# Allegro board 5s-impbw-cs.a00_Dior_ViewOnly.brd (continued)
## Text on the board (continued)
User.45: list("[Package] BOTTOM" "Pkg to Place Keepin Spacing" "0 MIL [NONE]" "2968.44 MIL" "-2968.44 MIL" "DRC ERROR CLASS/PACKAGE_BOTTOM" "[Shape] Package Keepin/All ((9791.94 -9293.68) (17182.26 -5761.63))" "[Shape] Package Geometry/Place_Bound_Bottom ((9326.1 -2815.82) (9426.06 -2715.85))" list(9791.940000 -5761.630000) nil)@@@list("liquid_ni" "2014/02/18 09:29:22" nil "s0dcoa16607a" "5s-impbw-cs.104")@@@list("jake_ma" "2014/02/18 09:53:02" nil "s0dcoa89107" "5s-impbw-cs.104") | list("[Package] TOP" "Pkg to Place Keepin Spacing" "0 MIL [NONE]" "3167.02 MIL" "-3167.02 MIL" "DRC ERROR CLASS/PACKAGE_TOP" "[Shape] Package Keepin/All ((9791.94 -9293.68) (17182.26 -5761.63))" "[Shape] Package Geometry/Place_Bound_Top ((9326.1 -2615.82) (9426.06 -2515.85))" list(9791.940000 -5761.630000) nil)@@@list("liquid_ni" "2014/02/18 09:29:01" nil "s0dcoa16607a" "5s-impbw-cs.104")@@@list("jake_ma" "2014/02/18 09:52:38" nil "s0dcoa89107" "5s-impbw-cs.104") | list("[Package] TOP" "Pkg to Place Keepin Spacing" "0 MIL [NONE]" "3465.67 MIL" "-3465.67 MIL" "DRC ERROR CLASS/PACKAGE_TOP" "[Shape] Package Keepin/All ((9791.94 -9293.68) (17182.26 -5761.63))" "[Shape] Package Geometry/Place_Bound_Top ((9281.08 -2310.84) (9471.08 -2120.84))" list(9791.940000 -5761.630000) nil)@@@list("liquid_ni" "2014/02/18 09:29:00" nil "s0dcoa16607a" "5s-impbw-cs.104")@@@list("jake_ma" "2014/02/18 09:52:26" nil "s0dcoa89107" "5s-impbw-cs.104") | list("[Package] TOP" "Pkg to Place Keepin Spacing" "0 MIL [NONE]" "0 MIL" "0.00 MIL" "DRC ERROR CLASS/PACKAGE_TOP" "[Shape] Package Keepin/All ((9791.94 -9293.68) (17182.26 -5761.63))" "[Shape] Package Geometry/Place_Bound_Top ((9763.0 -7637.0) (9946.0 -7454.0))" list(9791.940000 -7637.000000) nil)@@@list("liquid_ni" "2014/02/18 09:29:04" nil "s0dcoa16607a" "5s-impbw-cs.104")@@@list("jake_ma" "2014/02/18 09:52:42" nil "s0dcoa89107" "5s-impbw-cs.104") | list("[Package] TOP" "Pkg to Place Keepin Spacing" "0 MIL [NONE]" "0 MIL" "0.00 MIL" "DRC ERROR CLASS/PACKAGE_TOP" "[Shape] Package Keepin/All ((9791.94 -9293.68) (17182.26 -5761.63))" "[Shape] Package Geometry/Place_Bound_Top ((9763.0 -7844.0) (9946.0 -7661.0))" list(9791.940000 -7844.000000) nil)@@@list("liquid_ni" "2014/02/18 09:29:04" nil "s0dcoa16607a" "5s-impbw-cs.104")@@@list("jake_ma" "2014/02/18 09:52:41" nil "s0dcoa89107" "5s-impbw-cs.104") | list("[Package] TOP" "Pkg to Place Keepin Spacing" "0 MIL [NONE]" "0 MIL" "0.00 MIL" "DRC ERROR CLASS/PACKAGE_TOP" "[Shape] Package Keepin/All ((9791.94 -9293.68) (17182.26 -5761.63))" "[Shape] Package Geometry/Place_Bound_Top ((9763.15 -8331.99) (9946.15 -8148.99))" list(9791.940000 -8331.990000) nil)@@@list("liquid_ni" "2014/02/18 09:28:53" nil "s0dcoa16607a" "5s-impbw-cs.104")@@@list("jake_ma" "2014/02/18 09:51:35" nil "s0dcoa89107" "5s-impbw-cs.104") | list("[Package] TOP" "Pkg to Place Keepin Spacing" "0 MIL [NONE]" "0 MIL" "0.00 MIL" "DRC ERROR CLASS/PACKAGE_TOP" "[Shape] Package Keepin/All ((9791.94 -9293.68) (17182.26 -5761.63))" "[Shape] Package Geometry/Place_Bound_Top ((9764.0 -8530.0) (9947.0 -8347.0))" list(9791.940000 -8530.000000) nil)@@@list("liquid_ni" "2014/02/18 09:29:03" nil "s0dcoa16607a" "5s-impbw-cs.104")@@@list("jake_ma" "2014/02/18 09:47:59" nil "s0dcoa89107" "5s-impbw-cs.104") | list("[Package] BOTTOM" "Pkg to Place Keepin Spacing" "0 MIL [NONE]" "365.88 MIL" "-365.88 MIL" "DRC ERROR CLASS/PACKAGE_BOTTOM" "[Shape] Package Keepin/All ((9791.94 -9293.68) (17182.26 -5761.63))" "[Shape] Package Geometry/Place_Bound_Bottom ((9326.1 -8638.67) (9426.06 -8538.7))" list(9791.940000 -8588.680000) nil)@@@list("liquid_ni" "2014/02/18 09:29:21" nil "s0dcoa16607a" "5s-impbw-cs.104")@@@list("jake_ma" "2014/02/18 09:53:01" nil "s0dcoa89107" "5s-impbw-cs.104") | list("[Package] TOP" "Pkg to Place Keepin Spacing" "0 MIL [NONE]" "0 MIL" "0.00 MIL" "DRC ERROR CLASS/PACKAGE_TOP" "[Shape] Package Keepin/All ((9791.94 -9293.68) (17182.26 -5761.63))" "[Shape] Package Geometry/Place_Bound_Top ((9763.5 -8729.0) (9947.0 -8543.0))" list(9791.940000 -8729.000000) nil)@@@list("liquid_ni" "2014/02/18 09:29:03" nil "s0dcoa16607a" "5s-impbw-cs.104")@@@list("jake_ma" "2014/02/18 09:47:58" nil "s0dcoa89107" "5s-impbw-cs.104") | list("[Package] TOP" "Pkg to Place Keepin Spacing" "0 MIL [NONE]" "365.88 MIL" "-365.88 MIL" "DRC ERROR CLASS/PACKAGE_TOP" "[Shape] Package Keepin/All ((9791.94 -9293.68) (17182.26 -5761.63))" "[Shape] Package Geometry/Place_Bound_Top ((9326.1 -8838.67) (9426.06 -8738.7))" list(9791.940000 -8788.680000) nil)@@@list("liquid_ni" "2014/02/18 09:29:01" nil "s0dcoa16607a" "5s-impbw-cs.104")@@@list("jake_ma" "2014/02/18 09:52:37" nil "s0dcoa89107" "5s-impbw-cs.104") | list("[Package] TOP" "Pkg to Place Keepin Spacing" "0 MIL [NONE]" "0 MIL" "0.00 MIL" "DRC ERROR CLASS/PACKAGE_TOP" "[Shape] Package Keepin/All ((9791.94 -9293.68) (17182.26 -5761.63))" "[Shape] Package Geometry/Place_Bound_Top ((9763.0 -8806.0) (9946.0 -8743.0))" list(9791.940000 -8806.000000) nil)@@@list("liquid_ni" "2014/02/18 09:29:02" nil "s0dcoa16607a" "5s-impbw-cs.104")@@@list("jake_ma" "2014/02/18 09:52:40" nil "s0dcoa89107" "5s-impbw-cs.104") | list("[Package] TOP" "Pkg to Place Keepin Spacing" "0 MIL [NONE]" "337.34 MIL" "-337.34 MIL" "DRC ERROR CLASS/PACKAGE_TOP" "[Shape] Package Keepin/All ((9791.94 -9293.68) (17182.26 -5761.63))" "[Shape] Package Geometry/Place_Bound_Top ((9281.08 -9233.68) (9471.08 -9043.68))" list(9791.940000 -8939.530000) nil)@@@list("liquid_ni" "2014/02/18 09:28:59" nil "s0dcoa16607a" "5s-impbw-cs.104")@@@list("jake_ma" "2014/02/18 09:52:00" nil "s0dcoa89107" "5s-impbw-cs.104") | list("[Electrical] ALL" "Diffpair Max Uncoupled Length" "200 MIL [DIFFP_UNCOUPLED_LENGTH]" "222.6 MIL" "-22.60 MIL" "DRC ERROR CLASS/ALL" "[PinPair] <uTiL>cId2972<uTiL>.37:<uTiL>cId3248<uTiL>.C22 ((9896.52 -5943.25) (10624.86 -7168.35))" "[PinPair] <uTiL>cId2972<uTiL>.38:<uTiL>cId3248<uTiL>.C23 ((9896.52 -5962.93) (10601.66 -7184.35))" list(9896.520000 -5962.930000) nil)@@@list("liquid_ni" "2014/02/18 09:28:51" nil "s0dcoa16607a" "5s-impbw-cs.104")@@@list("jake_ma" "2014/02/18 09:47:12" nil "s0dcoa89107" "5s-impbw-cs.104") | list("[Electrical] ALL" "Diffpair Max Uncoupled Length" "200 MIL [DIFFP_UNCOUPLED_LENGTH]" "235.45 MIL" "-35.45 MIL" "DRC ERROR CLASS/ALL" "[PinPair] <uTiL>cId2972<uTiL>.40:<uTiL>cId3248<uTiL>.E10 ((9896.52 -6002.3) (10657.66 -6884.13))" "[PinPair] <uTiL>cId2972<uTiL>.41:<uTiL>cId3248<uTiL>.F10 ((9896.52 -6021.99) (10683.26 -6884.13))" list(9896.520000 -6021.990000) nil)@@@list("liquid_ni" "2014/02/18 09:28:52" nil "s0dcoa16607a" "5s-impbw-cs.104")@@@list("jake_ma" "2014/02/18 09:47:14" nil "s0dcoa89107" "5s-impbw-cs.104") | list("[Electrical] ALL" "Diffpair Max Uncoupled Length" "200 MIL [DIFFP_UNCOUPLED_LENGTH]" "249.63 MIL" "-49.63 MIL" "DRC ERROR CLASS/ALL" "[PinPair] <uTiL>cId2972<uTiL>.44:<uTiL>cId3248<uTiL>.B37 ((9896.52 -6081.04) (10580.16 -7544.64))" "[PinPair] <uTiL>cId2972<uTiL>.43:<uTiL>cId3248<uTiL>.A37 ((9896.52 -6061.36) (10554.56 -7544.64))" list(9896.520000 -6061.360000) nil)@@@list("liquid_ni" "2014/02/18 09:28:49" nil "s0dcoa16607a" "5s-impbw-cs.104")@@@list("jake_ma" "2014/02/18 09:47:09" nil "s0dcoa89107" "5s-impbw-cs.104") | list("[Electrical] ALL" "Diffpair Max Uncoupled Length" "200 MIL [DIFFP_UNCOUPLED_LENGTH]" "212.84 MIL" "-12.84 MIL" "DRC ERROR CLASS/ALL" "[PinPair] <uTiL>cId3219<uTiL>.22:<uTiL>cId2972<uTiL>.58 ((11113.64 -5982.01) (9896.52 -6356.63))" "[PinPair] <uTiL>cId3219<uTiL>.23:<uTiL>cId2972<uTiL>.59 ((11093.95 -5982.01) (9896.52 -6376.32))" list(9896.520000 -6376.320000) nil)@@@list("liquid_ni" "2014/02/18 09:28:11" nil "s0dcoa16607a" "5s-impbw-cs.104")@@@list("jake_ma" "2014/02/18 09:45:26" nil "s0dcoa89107" "5s-impbw-cs.104") | list("[Package] BOTTOM" "Pkg to Pkg Spacing" "0 MIL [PACKAGE_HEIGHT_MIN]" "2 MIL" "-2.00 MIL" "DRC ERROR CLASS/PACKAGE_BOTTOM" "[Shape] Package Geometry/Place_Bound_Bottom ((9796.52 -7945.0) (10080.38 -7589.8))" "[Shape] Package Geometry/Place_Bound_Bottom ((9916.61 -7721.7) (9960.23 -7679.7))" list(9916.610000 -7589.800000) nil)@@@list("liquid_ni" "2014/02/18 09:29:14" nil "s0dcoa16607a" "5s-impbw-cs.104")@@@list("jake_ma" "2014/02/18 09:48:59" nil "s0dcoa89107" "5s-impbw-cs.104") | list("[Package] BOTTOM" "Pkg to Pkg Spacing" "0 MIL [PACKAGE_HEIGHT_MIN]" "2 MIL" "-2.00 MIL" "DRC ERROR CLASS/PACKAGE_BOTTOM" "[Shape] Package Geometry/Place_Bound_Bottom ((9796.52 -7945.0) (10080.38 -7589.8))" "[Shape] Package Geometry/Place_Bound_Bottom ((9921.48 -7856.0) (9965.1 -7814.0))" list(9965.100000 -7945.000000) nil)@@@list("liquid_ni" "2014/02/18 09:29:14" nil "s0dcoa16607a" "5s-impbw-cs.104")@@@list("jake_ma" "2014/02/18 09:49:01" nil "s0dcoa89107" "5s-impbw-cs.104") | list("[Package] BOTTOM" "Pkg to Pkg Spacing" "0 MIL [PACKAGE_HEIGHT_MIN]" "2 MIL" "-2.00 MIL" "DRC ERROR CLASS/PACKAGE_BOTTOM" "[Shape] Package Geometry/Place_Bound_Bottom ((9975.3 -8315.27) (10085.48 -8252.35))" "[Shape] Package Geometry/Place_Bound_Bottom ((9993.04 -8305.89) (10035.04 -8262.27))" list(9993.040000 -8305.890000) nil)@@@list("liquid_ni" "2014/02/18 09:29:12" nil "s0dcoa16607a" "5s-impbw-cs.104")@@@list("jake_ma" "2014/02/18 09:48:55" nil "s0dcoa89107" "5s-impbw-cs.104") | list("[Electrical] ALL" "Diffpair Max Uncoupled Length" "200 MIL [DIFFP_UNCOUPLED_LENGTH]" "339.37 MIL" "-139.37 MIL" "DRC ERROR CLASS/ALL" "[PinPair] <uTiL>cId3248<uTiL>.AN8:<uTiL>cId2972<uTiL>.6 ((11279.04 -6838.61) (10069.74 -5923.56))" "[PinPair] <uTiL>cId3248<uTiL>.AM8:<uTiL>cId2972<uTiL>.7 ((11253.44 -6838.61) (10069.74 -5943.25))" list(10069.740000 -5943.250000) nil)@@@list("liquid_ni" "2014/02/18 09:28:42" nil "s0dcoa16607a" "5s-impbw-cs.104")@@@list("jake_ma" "2014/02/18 09:46:54" nil "s0dcoa89107" "5s-impbw-cs.104") | list("[Package] BOTTOM" "Pkg to Place Keepin Spacing" "0 MIL [NONE]" "0 MIL" "0.00 MIL" "DRC ERROR CLASS/PACKAGE_BOTTOM" "[Shape] Package Keepin/All ((9791.94 -9293.68) (17182.26 -5761.63))" "[Shape] Package Geometry/Place_Bound_Bottom ((9845.01 -6480.85) (10121.25 -5740.29))" list(10085.690000 -5761.630000) nil)@@@list("liquid_ni" "2014/02/18 09:29:20" nil "s0dcoa16607a" "5s-impbw-cs.104")@@@list("jake_ma" "2014/02/18 09:52:58" nil "s0dcoa89107" "5s-impbw-cs.104") | list("[Package] BOTTOM" "Pkg to Place Keepin Spacing" "0 MIL [NONE]" "0 MIL" "0.00 MIL" "DRC ERROR CLASS/PACKAGE_BOTTOM" "[Shape] Package Keepin/All ((9791.94 -9293.68) (17182.26 -5761.63))" "[Shape] Package Geometry/Place_Bound_Bottom ((9805.48 -9358.57) (10121.48 -8964.46))" list(10121.480000 -9293.680000) nil)@@@list("liquid_ni" "2014/02/18 09:29:06" nil "s0dcoa16607a" "5s-impbw-cs.104")@@@list("jake_ma" "2014/02/18 09:52:50" nil "s0dcoa89107" "5s-impbw-cs.104") | list("[Package] TOP" "Pkg to Place Keepin Spacing" "0 MIL [NONE]" "0 MIL" "0.00 MIL" "DRC ERROR CLASS/PACKAGE_TOP" "[Shape] Package Keepin/All ((9791.94 -9293.68) (17182.26 -5761.63))" "[Shape] Package Geometry/Place_Bound_Top ((9805.48 -9358.57) (10121.48 -8964.46))" list(10121.480000 -9293.680000) nil)@@@list("liquid_ni" "2014/02/18 09:28:54" nil "s0dcoa16607a" "5s-impbw-cs.104")@@@list("jake_ma" "2014/02/18 09:51:39" nil "s0dcoa89107" "5s-impbw-cs.104") | list("[Package] TOP" "Pkg to Pkg Spacing" "0 MIL [PACKAGE_HEIGHT_MIN]" "2 MIL" "-2.00 MIL" "DRC ERROR CLASS/PACKAGE_TOP" "[Shape] Package Geometry/Place_Bound_Top ((10162.99 -7893.13) (10212.83 -7783.13))" "[Shape] Package Geometry/Place_Bound_Top ((10145.68 -7837.31) (10187.68 -7793.69))" list(10162.990000 -7837.310000) nil)@@@list("liquid_ni" "2014/02/18 09:28:58" nil "s0dcoa16607a" "5s-impbw-cs.104")@@@list("jake_ma" "2014/02/18 09:47:43" nil "s0dcoa89107" "5s-impbw-cs.104") | list("[Package] TOP" "Pkg to Pkg Spacing" "0 MIL [PACKAGE_HEIGHT_MIN]" "2 MIL" "-2.00 MIL" "DRC ERROR CLASS/PACKAGE_TOP" "[Shape] Package Geometry/Place_Bound_Top ((10162.99 -7893.13) (10212.83 -7783.13))" "[Shape] Package Geometry/Place_Bound_Top ((10147.0 -7887.81) (10189.0 -7844.19))" list(10162.990000 -7887.810000) nil)@@@list("liquid_ni" "2014/02/18 09:28:58" nil "s0dcoa16607a" "5s-impbw-cs.104")@@@list("jake_ma" "2014/02/18 09:47:44" nil "s0dcoa89107" "5s-impbw-cs.104") | list("[Package] BOTTOM" "Pkg to Place Keepin Spacing" "0 MIL [NONE]" "0 MIL" "0.00 MIL" "DRC ERROR CLASS/PACKAGE_BOTTOM" "[Shape] Package Keepin/All ((9791.94 -9293.68) (17182.26 -5761.63))" "[Shape] Package Geometry/Place_Bound_Bottom ((10179.49 -6012.42) (10495.49 -5696.42))" list(10179.490000 -5761.630000) nil)@@@list("liquid_ni" "2014/02/18 09:29:07" nil "s0dcoa16607a" "5s-impbw-cs.104")@@@list("jake_ma" "2014/02/18 09:52:51" nil "s0dcoa89107" "5s-impbw-cs.104") | list("[Package] TOP" "Pkg to Place Keepin Spacing" "0 MIL [NONE]" "0 MIL" "0.00 MIL" "DRC ERROR CLASS/PACKAGE_TOP" "[Shape] Package Keepin/All ((9791.94 -9293.68) (17182.26 -5761.63))" "[Shape] Package Geometry/Place_Bound_Top ((10179.49 -6012.42) (10495.49 -5696.42))" list(10179.490000 -5761.630000) nil)@@@list("liquid_ni" "2014/02/18 09:28:54" nil "s0dcoa16607a" "5s-impbw-cs.104")@@@list("jake_ma" "2014/02/18 09:51:40" nil "s0dcoa89107" "5s-impbw-cs.104") | list("[Package] TOP" "Pkg to Pkg Spacing" "0 MIL [PACKAGE_HEIGHT_MIN]" "39.37 MIL" "-39.37 MIL" "DRC ERROR CLASS/PACKAGE_TOP" "[Shape] Package Geometry/Place_Bound_Top ((10274.4 -6767.73) (10318.02 -6725.73))" "[Shape] Package Geometry/Place_Bound_Top ((10215.61 -6834.76) (10387.63 -6693.0))" list(10274.400000 -6767.730000) nil)@@@list("liquid_ni" "2014/02/18 09:28:57" nil "s0dcoa16607a" "5s-impbw-cs.104")@@@list("jake_ma" "2014/02/18 09:47:35" nil "s0dcoa89107" "5s-impbw-cs.104") | list("[Package] TOP" "Pkg to Pkg Spacing" "0 MIL [PACKAGE_HEIGHT_MIN]" "2 MIL" "-2.00 MIL" "DRC ERROR CLASS/PACKAGE_TOP" "[Shape] Package Geometry/Place_Bound_Top ((10275.47 -6800.66) (10319.09 -6758.66))" "[Shape] Package Geometry/Place_Bound_Top ((10274.4 -6767.73) (10318.02 -6725.73))" list(10275.470000 -6758.660000) nil)@@@list("liquid_ni" "2014/02/18 09:28:58" nil "s0dcoa16607a" "5s-impbw-cs.104")@@@list("jake_ma" "2014/02/18 09:47:45" nil "s0dcoa89107" "5s-impbw-cs.104") | list("[Package] TOP" "Pkg to Pkg Spacing" "0 MIL [PACKAGE_HEIGHT_MIN]" "39.37 MIL" "-39.37 MIL" "DRC ERROR CLASS/PACKAGE_TOP" "[Shape] Package Geometry/Place_Bound_Top ((10275.47 -6800.66) (10319.09 -6758.66))" "[Shape] Package Geometry/Place_Bound_Top ((10215.61 -6834.76) (10387.63 -6693.0))" list(10275.470000 -6800.660000) nil)@@@list("liquid_ni" "2014/02/18 09:28:56" nil "s0dcoa16607a" "5s-impbw-cs.104")@@@list("jake_ma" "2014/02/18 09:47:33" nil "s0dcoa89107" "5s-impbw-cs.104") | list("[Package] BOTTOM" "Pkg to Pkg Spacing" "0 MIL [PACKAGE_HEIGHT_MIN]" "120 MIL" "-120.00 MIL" "DRC ERROR CLASS/PACKAGE_BOTTOM" "[Shape] Package Geometry/Place_Bound_Bottom ((10490.84 -6102.57) (10971.54 -5779.49))" "[Shape] Package Geometry/Place_Bound_Bottom ((10179.49 -6012.42) (10495.49 -5696.42))" list(10495.490000 -5964.530000) nil)@@@list("liquid_ni" "2014/02/18 09:29:07" nil "s0dcoa16607a" "5s-impbw-cs.104")@@@list("jake_ma" "2014/02/18 09:48:09" nil "s0dcoa89107" "5s-impbw-cs.104") | list("[Electrical] ALL" "Diffpair Max Uncoupled Length" "200 MIL [DIFFP_UNCOUPLED_LENGTH]" "216.22 MIL" "-16.22 MIL" "DRC ERROR CLASS/ALL" "[PinPair] <uTiL>cId3248<uTiL>.B15:<uTiL>cId3240<uTiL>.2 ((10579.86 -7034.35) (16685.2 -7384.77))" "[PinPair] <uTiL>cId3248<uTiL>.A15:<uTiL>cId3240<uTiL>.1 ((10554.56 -7021.35) (16665.52 -7384.77))" list(10554.560000 -7021.350000) nil)@@@list("liquid_ni" "2014/02/18 09:28:21" nil "s0dcoa16607a" "5s-impbw-cs.104")@@@list("jake_ma" "2014/02/18 09:45:48" nil "s0dcoa89107" "5s-impbw-cs.104") | list("[Electrical] ALL" "Diffpair Max Uncoupled Length" "200 MIL [DIFFP_UNCOUPLED_LENGTH]" "226.08 MIL" "-26.08 MIL" "DRC ERROR CLASS/ALL" "[PinPair] <uTiL>cId3248<uTiL>.B45:<uTiL>cId3239<uTiL>.61 ((10580.16 -7742.08) (16287.99 -8365.55))" "[PinPair] <uTiL>cId3248<uTiL>.A45:<uTiL>cId3239<uTiL>.60 ((10554.56 -7742.08) (16287.99 -8381.3))" list(10554.560000 -7742.080000) nil)@@@list("liquid_ni" "2014/02/18 09:28:17" nil "s0dcoa16607a" "5s-impbw-cs.104")@@@list("jake_ma" "2014/02/18 09:45:39" nil "s0dcoa89107" "5s-impbw-cs.104") | list("[Electrical] ALL" "Diffpair Max Uncoupled Length" "200 MIL [DIFFP_UNCOUPLED_LENGTH]" "299.45 MIL" "-99.45 MIL" "DRC ERROR CLASS/ALL" "[PinPair] <uTiL>cId3248<uTiL>.A17:<uTiL>cId3779<uTiL>.47 ((10554.56 -7050.85) (13530.6 -8518.56))" "[PinPair] <uTiL>cId3248<uTiL>.B17:<uTiL>cId3779<uTiL>.49 ((10579.86 -7064.75) (13530.6 -8538.25))" list(10579.860000 -7064.750000) nil)@@@list("liquid_ni" "2014/02/18 09:28:19" nil "s0dcoa16607a" "5s-impbw-cs.104")@@@list("jake_ma" "2014/02/18 09:45:43" nil "s0dcoa89107" "5s-impbw-cs.104") | list("[Electrical] ALL" "Diffpair Max Uncoupled Length" "200 MIL [DIFFP_UNCOUPLED_LENGTH]" "451.68 MIL" "-251.68 MIL" "DRC ERROR CLASS/ALL" "[PinPair] <uTiL>cId3220<uTiL>.9:<uTiL>cId3248<uTiL>.A33 ((10685.32 -6063.67) (10554.56 -7445.92))" "[PinPair] <uTiL>cId3220<uTiL>.8:<uTiL>cId3248<uTiL>.B33 ((10665.63 -6063.67) (10580.16 -7445.92))" list(10580.160000 -7445.920000) nil)@@@list("liquid_ni" "2014/02/18 09:28:14" nil "s0dcoa16607a" "5s-impbw-cs.104")@@@list("jake_ma" "2014/02/18 09:45:33" nil "s0dcoa89107" "5s-impbw-cs.104") | list("[Electrical] ALL" "Diffpair Max Uncoupled Length" "200 MIL [DIFFP_UNCOUPLED_LENGTH]" "256.91 MIL" "-56.91 MIL" "DRC ERROR CLASS/ALL" "[PinPair] <uTiL>cId3248<uTiL>.B30:<uTiL>cId3778<uTiL>.35 ((10592.96 -7369.38) (16861.23 -7356.26))" "[PinPair] <uTiL>cId3248<uTiL>.C29:<uTiL>cId3778<uTiL>.37 ((10605.76 -7347.2) (16861.23 -7336.57))" list(10605.760000 -7347.200000) nil)@@@list("liquid_ni" "2014/02/18 09:28:22" nil "s0dcoa16607a" "5s-impbw-cs.104")@@@list("jake_ma" "2014/02/18 09:45:51" nil "s0dcoa89107" "5s-impbw-cs.104") | list("[Electrical] ALL" "Diffpair Max Uncoupled Length" "200 MIL [DIFFP_UNCOUPLED_LENGTH]" "768.04 MIL" "-568.04 MIL" "DRC ERROR CLASS/ALL" "[PinPair] <uTiL>cId3219<uTiL>.9:<uTiL>cId3248<uTiL>.B34 ((11113.64 -6127.67) (10592.96 -7468.1))" "[PinPair] <uTiL>cId3219<uTiL>.8:<uTiL>cId3248<uTiL>.C33 ((11093.95 -6127.67) (10605.76 -7445.92))" list(10605.760000 -7445.920000) nil)@@@list("liquid_ni" "2014/02/18 09:28:15" nil "s0dcoa16607a" "5s-impbw-cs.104")@@@list("jake_ma" "2014/02/18 09:45:35" nil "s0dcoa89107" "5s-impbw-cs.104") | list("[Electrical] ALL" "Diffpair Max Uncoupled Length" "200 MIL [DIFFP_UNCOUPLED_LENGTH]" "734.16 MIL" "-534.16 MIL" "DRC ERROR CLASS/ALL" "[PinPair] <uTiL>cId3220<uTiL>.12:<uTiL>cId3248<uTiL>.F18 ((10744.37 -6063.67) (10683.26 -7071.63))" "[PinPair] <uTiL>cId3220<uTiL>.11:<uTiL>cId3248<uTiL>.E18 ((10724.69 -6063.67) (10657.66 -7071.63))" list(10657.660000 -7071.630000) nil)@@@list("liquid_ni" "2014/02/18 09:28:11" nil "s0dcoa16607a" "5s-impbw-cs.104")@@@list("jake_ma" "2014/02/18 09:45:27" nil "s0dcoa89107" "5s-impbw-cs.104") | list("[Electrical] ALL" "Diffpair Max Uncoupled Length" "200 MIL [DIFFP_UNCOUPLED_LENGTH]" "463.4 MIL" "-263.40 MIL" "DRC ERROR CLASS/ALL" "[PinPair] <uTiL>cId3220<uTiL>.8:<uTiL>cId3248<uTiL>.B33 ((10665.63 -6063.67) (10580.16 -7445.92))" "[PinPair] <uTiL>cId3220<uTiL>.9:<uTiL>cId3248<uTiL>.A33 ((10685.32 -6063.67) (10554.56 -7445.92))" list(10685.320000 -6063.670000) nil)@@@list("liquid_ni" "2014/02/18 09:28:14" nil "s0dcoa16607a" "5s-impbw-cs.104")@@@list("jake_ma" "2014/02/18 09:45:34" nil "s0dcoa89107" "5s-impbw-cs.104") | list("[Electrical] ALL" "Diffpair Max Uncoupled Length" "200 MIL [DIFFP_UNCOUPLED_LENGTH]" "553.14 MIL" "-353.14 MIL" "DRC ERROR CLASS/ALL" "[PinPair] <uTiL>cId2640<uTiL>.4:<uTiL>cId3248<uTiL>.AR10 ((10770.56 -6069.06) (11317.44 -6891.94))" "[PinPair] <uTiL>cId2640<uTiL>.3:<uTiL>cId3248<uTiL>.AT10 ((10731.19 -6069.06) (11343.04 -6891.94))" list(10731.190000 -6069.060000) nil)@@@list("liquid_ni" "2014/02/18 09:28:20" nil "s0dcoa16607a" "5s-impbw-cs.104")@@@list("jake_ma" "2014/02/18 09:45:45" nil "s0dcoa89107" "5s-impbw-cs.104") | list("[Electrical] ALL" "Diffpair Max Uncoupled Length" "200 MIL [DIFFP_UNCOUPLED_LENGTH]" "637.12 MIL" "-437.12 MIL" "DRC ERROR CLASS/ALL" "[PinPair] <uTiL>cId3219<uTiL>.11:<uTiL>cId3248<uTiL>.G20 ((11153.01 -6127.67) (10708.86 -7109.13))" "[PinPair] <uTiL>cId3219<uTiL>.12:<uTiL>cId3248<uTiL>.H20 ((11172.69 -6127.67) (10734.46 -7109.13))" list(10734.460000 -7109.130000) nil)@@@list("liquid_ni" "2014/02/18 09:28:13" nil "s0dcoa16607a" "5s-impbw-cs.104")@@@list("jake_ma" "2014/02/18 09:45:29" nil "s0dcoa89107" "5s-impbw-cs.104") | list("[Electrical] ALL" "Diffpair Max Uncoupled Length" "200 MIL [DIFFP_UNCOUPLED_LENGTH]" "709.39 MIL" "-509.39 MIL" "DRC ERROR CLASS/ALL" "[PinPair] <uTiL>cId3220<uTiL>.11:<uTiL>cId3248<uTiL>.E18 ((10724.69 -6063.67) (10657.66 -7071.63))" "[PinPair] <uTiL>cId3220<uTiL>.12:<uTiL>cId3248<uTiL>.F18 ((10744.37 -6063.67) (10683.26 -7071.63))" list(10744.370000 -6063.670000) nil)@@@list("liquid_ni" "2014/02/18 09:28:12" nil "s0dcoa16607a" "5s-impbw-cs.104")@@@list("jake_ma" "2014/02/18 09:45:28" nil "s0dcoa89107" "5s-impbw-cs.104") | list("[Electrical] ALL" "Diffpair Max Uncoupled Length" "200 MIL [DIFFP_UNCOUPLED_LENGTH]" "242.72 MIL" "-42.72 MIL" "DRC ERROR CLASS/ALL" "[PinPair] <uTiL>cId3248<uTiL>.H5:<uTiL>cId3240<uTiL>.5 ((10734.46 -6771.63) (16744.26 -7384.77))" "[PinPair] <uTiL>cId3248<uTiL>.J5:<uTiL>cId3240<uTiL>.4 ((10760.06 -6772.63) (16724.58 -7384.77))" list(10760.060000 -6772.630000) nil)@@@list("liquid_ni" "2014/02/18 09:28:25" nil "s0dcoa16607a" "5s-impbw-cs.104")@@@list("jake_ma" "2014/02/18 09:45:55" nil "s0dcoa89107" "5s-impbw-cs.104") | list("[Electrical] ALL" "Diffpair Max Uncoupled Length" "200 MIL [DIFFP_UNCOUPLED_LENGTH]" "298.77 MIL" "-98.77 MIL" "DRC ERROR CLASS/ALL" "[PinPair] <uTiL>cId3248<uTiL>.H8:<uTiL>cId3779<uTiL>.41 ((10734.46 -6846.63) (13530.6 -8459.51))" "[PinPair] <uTiL>cId3248<uTiL>.J8:<uTiL>cId3779<uTiL>.43 ((10760.06 -6846.63) (13530.6 -8479.19))" list(10760.060000 -6846.630000) nil)@@@list("liquid_ni" "2014/02/18 09:28:17" nil "s0dcoa16607a" "5s-impbw-cs.104")@@@list("jake_ma" "2014/02/18 09:45:41" nil "s0dcoa89107" "5s-impbw-cs.104") | list("[Package] BOTTOM" "Pkg to Pkg Spacing" "0 MIL [PACKAGE_HEIGHT_MIN]" "21.65 MIL" "-21.65 MIL" "DRC ERROR CLASS/PACKAGE_BOTTOM" "[Shape] Package Geometry/Place_Bound_Bottom ((11020.5 -5868.91) (11146.88 -5797.65))" "[Shape] Package Geometry/Place_Bound_Bottom ((11022.67 -5876.59) (11144.71 -5789.97))" list(11022.670000 -5868.910000) nil)@@@list("liquid_ni" "2014/02/18 09:29:11" nil "s0dcoa16607a" "5s-impbw-cs.104")@@@list("jake_ma" "2014/02/18 09:48:52" nil "s0dcoa89107" "5s-impbw-cs.104") | list("[Electrical] ALL" "Diffpair Max Uncoupled Length" "200 MIL [DIFFP_UNCOUPLED_LENGTH]" "775.1 MIL" "-575.10 MIL" "DRC ERROR CLASS/ALL" "[PinPair] <uTiL>cId3219<uTiL>.8:<uTiL>cId3248<uTiL>.C33 ((11093.95 -6127.67) (10605.76 -7445.92))" "[PinPair] <uTiL>cId3219<uTiL>.9:<uTiL>cId3248<uTiL>.B34 ((11113.64 -6127.67) (10592.96 -7468.1))" list(11113.640000 -6127.670000) nil)@@@list("liquid_ni" "2014/02/18 09:28:16" nil "s0dcoa16607a" "5s-impbw-cs.104")@@@list("jake_ma" "2014/02/18 09:45:37" nil "s0dcoa89107" "5s-impbw-cs.104") | list("[Electrical] ALL" "Diffpair Max Uncoupled Length" "200 MIL [DIFFP_UNCOUPLED_LENGTH]" "645.86 MIL" "-445.86 MIL" "DRC ERROR CLASS/ALL" "[PinPair] <uTiL>cId3219<uTiL>.12:<uTiL>cId3248<uTiL>.H20 ((11172.69 -6127.67) (10734.46 -7109.13))" "[PinPair] <uTiL>cId3219<uTiL>.11:<uTiL>cId3248<uTiL>.G20 ((11153.01 -6127.67) (10708.86 -7109.13))" list(11153.010000 -6127.670000) nil)@@@list("liquid_ni" "2014/02/18 09:28:13" nil "s0dcoa16607a" "5s-impbw-cs.104")@@@list("jake_ma" "2014/02/18 09:45:31" nil "s0dcoa89107" "5s-impbw-cs.104") | list("[Electrical] ALL" "Diffpair Max Uncoupled Length" "200 MIL [DIFFP_UNCOUPLED_LENGTH]" "338.85 MIL" "-138.85 MIL" "DRC ERROR CLASS/ALL" "[PinPair] <uTiL>cId3248<uTiL>.AM13:<uTiL>cId3241<uTiL>.37 ((11240.64 -6967.47) (16043.27 -6653.65))" "[PinPair] <uTiL>cId3248<uTiL>.AN13:<uTiL>cId3241<uTiL>.38 ((11266.24 -6967.47) (16023.58 -6653.65))" list(11266.240000 -6967.470000) nil)@@@list("liquid_ni" "2014/02/18 09:28:44" nil "s0dcoa16607a" "5s-impbw-cs.104")@@@list("jake_ma" "2014/02/18 09:46:59" nil "s0dcoa89107" "5s-impbw-cs.104") | list("[Electrical] ALL" "Relative Propagation Delay" "R_DDR_A_CTL:G::::100.00 MIL [RELATIVE_PROPAGATION_DELAY]" "113 MIL" "" "DRC ERROR CLASS/ALL" "[PinPair] <uTiL>cId3248<uTiL>.AR32:<uTiL>cId3245<uTiL>.L1 ((11322.96 -7410.31) (12895.83 -8464.31))" "[PinPair] <uTiL>cId3248<uTiL>.AP33:<uTiL>cId3243<uTiL>.L2 ((11297.36 -7445.81) (12895.83 -7198.78))" list(11297.360000 -7445.810000) nil)@@@list("liquid_ni" "2014/02/18 09:28:29" nil "s0dcoa16607a" "5s-impbw-cs.104")@@@list("jake_ma" "2014/02/18 09:46:04" nil "s0dcoa89107" "5s-impbw-cs.104") | list("[Electrical] ALL" "Relative Propagation Delay" "R_DDR_A_CTL:G::::100.00 MIL [RELATIVE_PROPAGATION_DELAY]" "113.36 MIL" "" "DRC ERROR CLASS/ALL" "[PinPair] <uTiL>cId3248<uTiL>.AR32:<uTiL>cId3245<uTiL>.L1 ((11322.96 -7410.31) (12895.83 -8464.31))" "[PinPair] <uTiL>cId3248<uTiL>.AP33:<uTiL>cId3244<uTiL>.L2 ((11297.36 -7445.81) (12895.83 -7978.74))" list(11297.360000 -7445.810000) nil)@@@list("liquid_ni" "2014/02/18 09:28:30" nil "s0dcoa16607a" "5s-impbw-cs.104")@@@list("jake_ma" "2014/02/18 09:46:06" nil "s0dcoa89107" "5s-impbw-cs.104") | list("[Electrical] ALL" "Relative Propagation Delay" "R_DDR_A_CTL:G::::100.00 MIL [RELATIVE_PROPAGATION_DELAY]" "115.33 MIL" "" "DRC ERROR CLASS/ALL" "[PinPair] <uTiL>cId3248<uTiL>.AR32:<uTiL>cId3245<uTiL>.L1 ((11322.96 -7410.31) (12895.83 -8464.31))" "[PinPair] <uTiL>cId3248<uTiL>.AP33:<uTiL>cId3242<uTiL>.L2 ((11297.36 -7445.81) (12895.83 -6744.7))" list(11297.360000 -7445.810000) nil)@@@list("liquid_ni" "2014/02/18 09:28:28" nil "s0dcoa16607a" "5s-impbw-cs.104")@@@list("jake_ma" "2014/02/18 09:46:03" nil "s0dcoa89107" "5s-impbw-cs.104") | list("[Electrical] ALL" "Relative Propagation Delay" "R_DDR_A_CLK_U2:G:::-100.00 MIL:100.00 MIL [RELATIVE_PROPAGATION_DELAY]" "129.04 MIL" "" "DRC ERROR CLASS/ALL" "[PinPair] <uTiL>cId3248<uTiL>.AV37:<uTiL>cId3245<uTiL>.J7 ((11394.24 -7552.04) (12832.84 -8275.34))" "[PinPair] <uTiL>cId3248<uTiL>.AR32:<uTiL>cId3245<uTiL>.L1 ((11322.96 -7410.31) (12895.83 -8464.31))" list(11322.960000 -7410.310000) nil)@@@list("liquid_ni" "2014/02/18 09:28:26" nil "s0dcoa16607a" "5s-impbw-cs.104")@@@list("jake_ma" "2014/02/18 09:45:57" nil "s0dcoa89107" "5s-impbw-cs.104") | list("[Electrical] ALL" "Relative Propagation Delay" "R_DDR_A_CTL:G::::100.00 MIL [RELATIVE_PROPAGATION_DELAY]" "109.5 MIL" "" "DRC ERROR CLASS/ALL" "[PinPair] <uTiL>cId3248<uTiL>.AU43:<uTiL>cId3243<uTiL>.K9 ((11368.64 -7703.59) (12864.33 -6978.31))" "[PinPair] <uTiL>cId3248<uTiL>.AR32:<uTiL>cId3244<uTiL>.L1 ((11322.96 -7410.31) (12895.83 -8010.23))" list(11322.960000 -7410.310000) nil)@@@list("liquid_ni" "2014/02/18 09:28:28" nil "s0dcoa16607a" "5s-impbw-cs.104")@@@list("jake_ma" "2014/02/18 09:46:02" nil "s0dcoa89107" "5s-impbw-cs.104") | list("[Electrical] ALL" "Relative Propagation Delay" "R_DDR_A_CTL:G::::100.00 MIL [RELATIVE_PROPAGATION_DELAY]" "111.18 MIL" "" "DRC ERROR CLASS/ALL" "[PinPair] <uTiL>cId3248<uTiL>.AU43:<uTiL>cId3243<uTiL>.K9 ((11368.64 -7703.59) (12864.33 -6978.31))" "[PinPair] <uTiL>cId3248<uTiL>.AR32:<uTiL>cId3243<uTiL>.L1 ((11322.96 -7410.31) (12895.83 -7230.27))" list(11322.960000 -7410.310000) nil)@@@list("liquid_ni" "2014/02/18 09:28:27" nil "s0dcoa16607a" "5s-impbw-cs.104")@@@list("jake_ma" "2014/02/18 09:46:00" nil "s0dcoa89107" "5s-impbw-cs.104") | list("[Electrical] ALL" "Relative Propagation Delay" "R_DDR_A_CTL:G::::100.00 MIL [RELATIVE_PROPAGATION_DELAY]" "116.78 MIL" "" "DRC ERROR CLASS/ALL" "[PinPair] <uTiL>cId3248<uTiL>.AU43:<uTiL>cId3243<uTiL>.K9 ((11368.64 -7703.59) (12864.33 -6978.31))" "[PinPair] <uTiL>cId3248<uTiL>.AR32:<uTiL>cId3242<uTiL>.L1 ((11322.96 -7410.31) (12895.83 -6776.19))" list(11322.960000 -7410.310000) nil)@@@list("liquid_ni" "2014/02/18 09:28:26" nil "s0dcoa16607a" "5s-impbw-cs.104")@@@list("jake_ma" "2014/02/18 09:45:58" nil "s0dcoa89107" "5s-impbw-cs.104") | list("[Electrical] ALL" "Relative Propagation Delay" "R_DDR_A_CTL:G::::100.00 MIL [RELATIVE_PROPAGATION_DELAY]" "131.6 MIL" "" "DRC ERROR CLASS/ALL" "[PinPair] <uTiL>cId3248<uTiL>.AR32:<uTiL>cId3245<uTiL>.L1 ((11322.96 -7410.31) (12895.83 -8464.31))" "[PinPair] <uTiL>cId3248<uTiL>.AU43:<uTiL>cId3244<uTiL>.K9 ((11368.64 -7703.59) (12864.33 -7758.27))" list(11368.640000 -7703.590000) nil)@@@list("liquid_ni" "2014/02/18 09:28:32" nil "s0dcoa16607a" "5s-impbw-cs.104")@@@list("jake_ma" "2014/02/18 09:46:09" nil "s0dcoa89107" "5s-impbw-cs.104") | list("[Electrical] ALL" "Relative Propagation Delay" "R_DDR_A_CTL:G::::100.00 MIL [RELATIVE_PROPAGATION_DELAY]" "141.93 MIL" "" "DRC ERROR CLASS/ALL" "[PinPair] <uTiL>cId3248<uTiL>.AR32:<uTiL>cId3245<uTiL>.L1 ((11322.96 -7410.31) (12895.83 -8464.31))" "[PinPair] <uTiL>cId3248<uTiL>.AU43:<uTiL>cId3242<uTiL>.K9 ((11368.64 -7703.59) (12864.33 -6524.23))" list(11368.640000 -7703.590000) nil)@@@list("liquid_ni" "2014/02/18 09:28:31" nil "s0dcoa16607a" "5s-impbw-cs.104")@@@list("jake_ma" "2014/02/18 09:46:07" nil "s0dcoa89107" "5s-impbw-cs.104") | list("[Electrical] ALL" "Relative Propagation Delay" "R_DDR_A_CTL:G::::100.00 MIL [RELATIVE_PROPAGATION_DELAY]" "143.38 MIL" "" "DRC ERROR CLASS/ALL" "[PinPair] <uTiL>cId3248<uTiL>.AR32:<uTiL>cId3245<uTiL>.L1 ((11322.96 -7410.31) (12895.83 -8464.31))" "[PinPair] <uTiL>cId3248<uTiL>.AU43:<uTiL>cId3245<uTiL>.K9 ((11368.64 -7703.59) (12864.33 -8212.35))" list(11368.640000 -7703.590000) nil)@@@list("liquid_ni" "2014/02/18 09:28:33" nil "s0dcoa16607a" "5s-impbw-cs.104")@@@list("jake_ma" "2014/02/18 09:46:11" nil "s0dcoa89107" "5s-impbw-cs.104") | list("[Electrical] ALL" "Relative Propagation Delay" "R_DDR_A_CTL:G::::100.00 MIL [RELATIVE_PROPAGATION_DELAY]" "147.88 MIL" "" "DRC ERROR CLASS/ALL" "[PinPair] <uTiL>cId3248<uTiL>.AR32:<uTiL>cId3245<uTiL>.L1 ((11322.96 -7410.31) (12895.83 -8464.31))" "[PinPair] <uTiL>cId3248<uTiL>.AU43:<uTiL>cId3243<uTiL>.K9 ((11368.64 -7703.59) (12864.33 -6978.31))" list(11368.640000 -7703.590000) nil)@@@list("liquid_ni" "2014/02/18 09:28:31" nil "s0dcoa16607a" "5s-impbw-cs.104")@@@list("jake_ma" "2014/02/18 09:46:08" nil "s0dcoa89107" "5s-impbw-cs.104") | list("[Electrical] ALL" "Relative Propagation Delay" "R_DDR_A_CTL:G::::100.00 MIL [RELATIVE_PROPAGATION_DELAY]" "113.2 MIL" "" "DRC ERROR CLASS/ALL" "[PinPair] <uTiL>cId3248<uTiL>.AR32:<uTiL>cId3245<uTiL>.L1 ((11322.96 -7410.31) (12895.83 -8464.31))" "[PinPair] <uTiL>cId3248<uTiL>.AW43:<uTiL>cId3244<uTiL>.J9 ((11419.84 -7705.54) (12832.84 -7758.27))" list(11419.840000 -7705.540000) nil)@@@list("liquid_ni" "2014/02/18 09:28:34" nil "s0dcoa16607a" "5s-impbw-cs.104")@@@list("jake_ma" "2014/02/18 09:46:13" nil "s0dcoa89107" "5s-impbw-cs.104") | list("[Electrical] ALL" "Relative Propagation Delay" "R_DDR_A_CTL:G::::100.00 MIL [RELATIVE_PROPAGATION_DELAY]" "128.42 MIL" "" "DRC ERROR CLASS/ALL" "[PinPair] <uTiL>cId3248<uTiL>.AR32:<uTiL>cId3245<uTiL>.L1 ((11322.96 -7410.31) (12895.83 -8464.31))" "[PinPair] <uTiL>cId3248<uTiL>.AW43:<uTiL>cId3245<uTiL>.J9 ((11419.84 -7705.54) (12832.84 -8212.35))" list(11419.840000 -7705.540000) nil)@@@list("liquid_ni" "2014/02/18 09:28:35" nil "s0dcoa16607a" "5s-impbw-cs.104")@@@list("jake_ma" "2014/02/18 09:46:14" nil "s0dcoa89107" "5s-impbw-cs.104") | list("[Electrical] ALL" "Relative Propagation Delay" "R_DDR_A_CTL:G::::100.00 MIL [RELATIVE_PROPAGATION_DELAY]" "138.42 MIL" "" "DRC ERROR CLASS/ALL" "[PinPair] <uTiL>cId3248<uTiL>.AR32:<uTiL>cId3245<uTiL>.L1 ((11322.96 -7410.31) (12895.83 -8464.31))" "[PinPair] <uTiL>cId3248<uTiL>.AW43:<uTiL>cId3243<uTiL>.J9 ((11419.84 -7705.54) (12832.84 -6978.31))" list(11419.840000 -7705.540000) nil)@@@list("liquid_ni" "2014/02/18 09:28:34" nil "s0dcoa16607a" "5s-impbw-cs.104")@@@list("jake_ma" "2014/02/18 09:46:12" nil "s0dcoa89107" "5s-impbw-cs.104") | list("[Electrical] ALL" "Diffpair Max Uncoupled Length" "200 MIL [DIFFP_UNCOUPLED_LENGTH]" "401.28 MIL" "-201.28 MIL" "DRC ERROR CLASS/ALL" "[PinPair] <uTiL>cId3248<uTiL>.AN21:<uTiL>cId3188<uTiL>.169 ((11271.76 -7131.93) (12089.27 -6596.53))" "[PinPair] <uTiL>cId3248<uTiL>.AM21:<uTiL>cId3188<uTiL>.171 ((11246.16 -7131.93) (12089.27 -6572.91))" list(12089.270000 -6572.910000) nil)@@@list("liquid_ni" "2014/02/18 09:28:45" nil "s0dcoa16607a" "5s-impbw-cs.104")@@@list("jake_ma" "2014/02/18 09:47:01" nil "s0dcoa89107" "5s-impbw-cs.104") | list("[Electrical] ALL" "Diffpair Max Uncoupled Length" "200 MIL [DIFFP_UNCOUPLED_LENGTH]" "558.67 MIL" "-358.67 MIL" "DRC ERROR CLASS/ALL" "[PinPair] <uTiL>cId3248<uTiL>.AN28:<uTiL>cId3188<uTiL>.45 ((11271.76 -7315.22) (12089.27 -8155.59))" "[PinPair] <uTiL>cId3248<uTiL>.AM28:<uTiL>cId3188<uTiL>.47 ((11246.16 -7315.22) (12089.27 -8131.97))" list(12089.270000 -8131.970000) nil)@@@list("liquid_ni" "2014/02/18 09:28:40" nil "s0dcoa16607a" "5s-impbw-cs.104")@@@list("jake_ma" "2014/02/18 09:46:52" nil "s0dcoa89107" "5s-impbw-cs.104") | list("[Package] BOTTOM" "Pkg to Place Keepout Spacing" "0 MIL [NONE]" "90.55 MIL" "-90.55 MIL" "DRC ERROR CLASS/PACKAGE_BOTTOM" "[Shape] Package Keepout/Bottom ((11399.94 -9452.82) (16518.41 -9220.96))" "[Shape] Package Geometry/Place_Bound_Bottom ((12313.86 -9223.84) (12810.14 -8904.39))" list(12313.860000 -9220.960000) nil)@@@list("liquid_ni" "2014/02/18 09:29:18" nil "s0dcoa16607a" "5s-impbw-cs.104")@@@list("jake_ma" "2014/02/18 09:49:10" nil "s0dcoa89107" "5s-impbw-cs.104") | list("[Electrical] ALL" "Relative Propagation Delay" "R_DDR_B_D7:G:::-5.00 MIL:23.00 MIL [RELATIVE_PROPAGATION_DELAY]" "32.99 MIL" "" "DRC ERROR CLASS/ALL" "[PinPair] <uTiL>cId3248<uTiL>.AM18:<uTiL>cId3188<uTiL>.188 ((11246.16 -7056.93) (12412.11 -6372.12))" "[PinPair] <uTiL>cId3188<uTiL>.194:<uTiL>cId3248<uTiL>.AP18 ((12412.11 -6301.26) (11297.36 -7056.93))" list(12412.110000 -6301.260000) nil)@@@list("liquid_ni" "2014/02/18 09:28:38" nil "s0dcoa16607a" "5s-impbw-cs.104")@@@list("jake_ma" "2014/02/18 09:46:27" nil "s0dcoa89107" "5s-impbw-cs.104") | list("[Electrical] ALL" "Relative Propagation Delay" "R_DDR_B_D7:G:::-5.00 MIL:23.00 MIL [RELATIVE_PROPAGATION_DELAY]" "32.44 MIL" "" "DRC ERROR CLASS/ALL" "[PinPair] <uTiL>cId3248<uTiL>.AM18:<uTiL>cId3188<uTiL>.188 ((11246.16 -7056.93) (12412.11 -6372.12))" "[PinPair] <uTiL>cId3188<uTiL>.192:<uTiL>cId3248<uTiL>.AR18 ((12412.11 -6324.88) (11322.96 -7056.93))" list(12412.110000 -6324.880000) nil)@@@list("liquid_ni" "2014/02/18 09:28:37" nil "s0dcoa16607a" "5s-impbw-cs.104")@@@list("jake_ma" "2014/02/18 09:46:24" nil "s0dcoa89107" "5s-impbw-cs.104") | list("[Electrical] ALL" "Diffpair Max Uncoupled Length" "200 MIL [DIFFP_UNCOUPLED_LENGTH]" "472.41 MIL" "-272.41 MIL" "DRC ERROR CLASS/ALL" "[PinPair] <uTiL>cId3248<uTiL>.AN18:<uTiL>cId3188<uTiL>.186 ((11271.76 -7056.93) (12412.11 -6395.75))" "[PinPair] <uTiL>cId3248<uTiL>.AM18:<uTiL>cId3188<uTiL>.188 ((11246.16 -7056.93) (12412.11 -6372.12))" list(12412.110000 -6372.120000) nil)@@@list("liquid_ni" "2014/02/18 09:28:39" nil "s0dcoa16607a" "5s-impbw-cs.104")@@@list("jake_ma" "2014/02/18 09:46:49" nil "s0dcoa89107" "5s-impbw-cs.104") | list("[Electrical] ALL" "Diffpair Max Uncoupled Length" "200 MIL [DIFFP_UNCOUPLED_LENGTH]" "222.12 MIL" "-22.12 MIL" "DRC ERROR CLASS/ALL" "[PinPair] <uTiL>cId3248<uTiL>.AW18:<uTiL>cId3188<uTiL>.154 ((11407.04 -7083.99) (12412.11 -6773.7))" "[PinPair] <uTiL>cId3248<uTiL>.AV18:<uTiL>cId3188<uTiL>.152 ((11381.44 -7083.99) (12412.11 -6797.32))" list(12412.110000 -6797.320000) nil)@@@list("liquid_ni" "2014/02/18 09:28:36" nil "s0dcoa16607a" "5s-impbw-cs.104")@@@list("jake_ma" "2014/02/18 09:46:19" nil "s0dcoa89107" "5s-impbw-cs.104") | list("[Electrical] ALL" "Diffpair Phase Tolerance" "5 [DIFFP_PHASE_TOL]" "19.83 MIL" "-14.83 MIL" "DRC ERROR CLASS/ALL" "[PinPair] <uTiL>cId3243<uTiL>.C7:<uTiL>cId3248<uTiL>.AW53 ((12643.86 -7041.3) (11407.04 -7942.09))" "[PinPair] <uTiL>cId3243<uTiL>.B7:<uTiL>cId3248<uTiL>.AV53 ((12612.37 -7041.3) (11381.44 -7942.09))" list(12612.370000 -7041.300000) nil)@@@list("liquid_ni" "2014/02/18 09:28:46" nil "s0dcoa16607a" "5s-impbw-cs.104")@@@list("jake_ma" "2014/02/18 09:47:02" nil "s0dcoa89107" "5s-impbw-cs.104") | list("[Electrical] ALL" "Relative Propagation Delay" "R_DDR_A_D5DQS:G:::0.00 MIL:1.00 MIL [RELATIVE_PROPAGATION_DELAY]" "19.83 MIL" "" "DRC ERROR CLASS/ALL" "[PinPair] <uTiL>cId3243<uTiL>.C7:<uTiL>cId3248<uTiL>.AW53 ((12643.86 -7041.3) (11407.04 -7942.09))" "[PinPair] <uTiL>cId3243<uTiL>.B7:<uTiL>cId3248<uTiL>.AV53 ((12612.37 -7041.3) (11381.44 -7942.09))" list(12612.370000 -7041.300000) nil)@@@list("liquid_ni" "2014/02/18 09:28:37" nil "s0dcoa16607a" "5s-impbw-cs.104")@@@list("jake_ma" "2014/02/18 09:46:21" nil "s0dcoa89107" "5s-impbw-cs.104") | list("[Electrical] ALL" "Diffpair Max Uncoupled Length" "200 MIL [DIFFP_UNCOUPLED_LENGTH]" "212.41 MIL" "-12.41 MIL" "DRC ERROR CLASS/ALL" "[PinPair] <uTiL>cId3248<uTiL>.AV57:<uTiL>cId3243<uTiL>.G3 ((11381.44 -8037.79) (12769.85 -7167.28))" "[PinPair] <uTiL>cId3248<uTiL>.AW57:<uTiL>cId3243<uTiL>.F3 ((11407.04 -8037.79) (12738.35 -7167.28))" list(12738.350000 -7167.280000) nil)@@@list("liquid_ni" "2014/02/18 09:28:48" nil "s0dcoa16607a" "5s-impbw-cs.104")@@@list("jake_ma" "2014/02/18 09:47:07" nil "s0dcoa89107" "5s-impbw-cs.104") | list("[Electrical] ALL" "Diffpair Max Uncoupled Length" "200 MIL [DIFFP_UNCOUPLED_LENGTH]" "267.37 MIL" "-67.37 MIL" "DRC ERROR CLASS/ALL" "[PinPair] <uTiL>cId1645<uTiL>.42:<uTiL>cId3248<uTiL>.B35 ((12789.27 -8932.25) (10580.16 -7490.28))" "[PinPair] <uTiL>cId1645<uTiL>.40:<uTiL>cId3248<uTiL>.A35 ((12769.58 -8932.25) (10554.56 -7490.28))" list(12769.580000 -8932.250000) nil)@@@list("liquid_ni" "2014/02/18 09:28:20" nil "s0dcoa16607a" "5s-impbw-cs.104")@@@list("jake_ma" "2014/02/18 09:45:46" nil "s0dcoa89107" "5s-impbw-cs.104") | list("[Electrical] ALL" "Diffpair Max Uncoupled Length" "200 MIL [DIFFP_UNCOUPLED_LENGTH]" "237.45 MIL" "-37.45 MIL" "DRC ERROR CLASS/ALL" "[PinPair] <uTiL>cId3242<uTiL>.F3:<uTiL>cId3248<uTiL>.AL49 ((12738.35 -6713.2) (11220.56 -7840.75))" "[PinPair] <uTiL>cId3242<uTiL>.G3:<uTiL>cId3248<uTiL>.AL48 ((12769.85 -6713.2) (11220.56 -7805.25))" list(12769.850000 -6713.200000) nil)@@@list("liquid_ni" "2014/02/18 09:28:47" nil "s0dcoa16607a" "5s-impbw-cs.104")@@@list("jake_ma" "2014/02/18 09:47:06" nil "s0dcoa89107" "5s-impbw-cs.104") | list("[Package] TOP" "Pkg to Place Keepout Spacing" "0 MIL [PACKAGE_HEIGHT_MIN]" "78.74 MIL" "-78.74 MIL" "DRC ERROR CLASS/PACKAGE_TOP" "[Shape] Package Geometry/Place_Bound_Top ((12910.41 -6356.26) (13410.81 -6033.03))" "[Shape] Package Keepout/Top ((13074.0 -6073.58) (13476.0 -5871.58))" list(13094.080000 -6033.030000) nil)@@@list("liquid_ni" "2014/02/18 09:28:52" nil "s0dcoa16607a" "5s-impbw-cs.104")@@@list("jake_ma" "2014/02/18 09:47:16" nil "s0dcoa89107" "5s-impbw-cs.104") | list("[Package] BOTTOM" "Pkg to Place Keepin Spacing" "0 MIL [NONE]" "0 MIL" "0.00 MIL" "DRC ERROR CLASS/PACKAGE_BOTTOM" "[Shape] Package Keepin/All ((9791.94 -9293.68) (17182.26 -5761.63))" "[Shape] Package Geometry/Place_Bound_Bottom ((13137.99 -6005.59) (13412.01 -5744.04))" list(13137.990000 -5761.630000) nil)@@@list("liquid_ni" "2014/02/18 09:29:05" nil "s0dcoa16607a" "5s-impbw-cs.104")@@@list("jake_ma" "2014/02/18 09:52:46" nil "s0dcoa89107" "5s-impbw-cs.104") | list("[Package] TOP" "Pkg to Pkg Spacing" "0 MIL [PACKAGE_HEIGHT_MIN]" "2 MIL" "-2.00 MIL" "DRC ERROR CLASS/PACKAGE_TOP" "[Shape] Package Geometry/Place_Bound_Top ((13318.76 -7290.79) (13358.76 -7217.59))" "[Shape] Package Geometry/Place_Bound_Top ((13335.0 -7293.81) (13377.0 -7250.19))" list(13358.760000 -7250.190000) nil)@@@list("liquid_ni" "2014/02/18 09:28:57" nil "s0dcoa16607a" "5s-impbw-cs.104")@@@list("jake_ma" "2014/02/18 09:47:42" nil "s0dcoa89107" "5s-impbw-cs.104") | list("[Package] BOTTOM" "Pkg to Pkg Spacing" "0 MIL [PACKAGE_HEIGHT_MIN]" "120 MIL" "-120.00 MIL" "DRC ERROR CLASS/PACKAGE_BOTTOM" "[Shape] Package Geometry/Place_Bound_Bottom ((13463.4 -7315.0) (13657.5 -6953.98))" "[Shape] Package Geometry/Place_Bound_Bottom ((13447.4 -7626.88) (13763.4 -7310.88))" list(13463.400000 -7315.000000) nil)@@@list("liquid_ni" "2014/02/18 09:29:08" nil "s0dcoa16607a" "5s-impbw-cs.104")@@@list("jake_ma" "2014/02/18 09:48:12" nil "s0dcoa89107" "5s-impbw-cs.104") | list("[Package] BOTTOM" "Pkg to Pkg Spacing" "0 MIL [PACKAGE_HEIGHT_MIN]" "2 MIL" "-2.00 MIL" "DRC ERROR CLASS/PACKAGE_BOTTOM" "[Shape] Package Geometry/Place_Bound_Bottom ((13463.4 -7315.0) (13657.5 -6953.98))" "[Shape] Package Geometry/Place_Bound_Bottom ((13544.83 -6984.5) (13588.45 -6942.5))" list(13544.830000 -6953.980000) nil)@@@list("liquid_ni" "2014/02/18 09:29:15" nil "s0dcoa16607a" "5s-impbw-cs.104")@@@list("jake_ma" "2014/02/18 09:49:03" nil "s0dcoa89107" "5s-impbw-cs.104") | list("[Package] BOTTOM" "Pkg to Pkg Spacing" "0 MIL [PACKAGE_HEIGHT_MIN]" "120 MIL" "-120.00 MIL" "DRC ERROR CLASS/PACKAGE_BOTTOM" "[Shape] Package Geometry/Place_Bound_Bottom ((13658.54 -7316.0) (13942.4 -6941.8))" "[Shape] Package Geometry/Place_Bound_Bottom ((13447.4 -7626.88) (13763.4 -7310.88))" list(13658.540000 -7316.000000) nil)@@@list("liquid_ni" "2014/02/18 09:29:08" nil "s0dcoa16607a" "5s-impbw-cs.104")@@@list("jake_ma" "2014/02/18 09:48:26" nil "s0dcoa89107" "5s-impbw-cs.104") | list("[Package] BOTTOM" "Pkg to Pkg Spacing" "0 MIL [PACKAGE_HEIGHT_MIN]" "2 MIL" "-2.00 MIL" "DRC ERROR CLASS/PACKAGE_BOTTOM" "[Shape] Package Geometry/Place_Bound_Bottom ((13879.91 -8970.46) (13990.09 -8907.54))" "[Shape] Package Geometry/Place_Bound_Bottom ((13929.0 -8961.81) (13971.0 -8918.19))" list(13929.000000 -8961.810000) nil)@@@list("liquid_ni" "2014/02/18 09:29:13" nil "s0dcoa16607a" "5s-impbw-cs.104")@@@list("jake_ma" "2014/02/18 09:48:58" nil "s0dcoa89107" "5s-impbw-cs.104") | list("[Package] BOTTOM" "Pkg to Pkg Spacing" "0 MIL [PACKAGE_HEIGHT_MIN]" "2 MIL" "-2.00 MIL" "DRC ERROR CLASS/PACKAGE_BOTTOM" "[Shape] Package Geometry/Place_Bound_Bottom ((13986.66 -9216.11) (14049.58 -9105.93))" "[Shape] Package Geometry/Place_Bound_Bottom ((14028.18 -9149.91) (14070.18 -9106.29))" list(14049.580000 -9149.910000) nil)@@@list("liquid_ni" "2014/02/18 09:29:13" nil "s0dcoa16607a" "5s-impbw-cs.104")@@@list("jake_ma" "2014/02/18 09:48:57" nil "s0dcoa89107" "5s-impbw-cs.104") | list("[Package] BOTTOM" "Pkg to Pkg Spacing" "0 MIL [PACKAGE_HEIGHT_MIN]" "118.11 MIL" "-118.11 MIL" "DRC ERROR CLASS/PACKAGE_BOTTOM" "[Shape] Package Geometry/Place_Bound_Bottom ((14028.18 -9149.91) (14070.18 -9106.29))" "[Shape] Package Geometry/Place_Bound_Bottom ((14054.44 -9113.78) (14307.0 -8904.72))" list(14070.180000 -9106.290000) nil)@@@list("liquid_ni" "2014/02/18 09:29:05" nil "s0dcoa16607a" "5s-impbw-cs.104")@@@list("jake_ma" "2014/02/18 09:48:06" nil "s0dcoa89107" "5s-impbw-cs.104") | list("[Package] BOTTOM" "Pkg to Pkg Spacing" "0 MIL [PACKAGE_HEIGHT_MIN]" "2 MIL" "-2.00 MIL" "DRC ERROR CLASS/PACKAGE_BOTTOM" "[Shape] Package Geometry/Place_Bound_Bottom ((14425.91 -7177.14) (14667.57 -7035.4))" "[Shape] Package Geometry/Place_Bound_Bottom ((14494.96 -7115.33) (14536.96 -7071.71))" list(14494.960000 -7115.330000) nil)@@@list("liquid_ni" "2014/02/18 09:29:15" nil "s0dcoa16607a" "5s-impbw-cs.104")@@@list("jake_ma" "2014/02/18 09:49:04" nil "s0dcoa89107" "5s-impbw-cs.104") | list("[Package] BOTTOM" "Pkg to Pkg Spacing" "0 MIL [PACKAGE_HEIGHT_MIN]" "39.37 MIL" "-39.37 MIL" "DRC ERROR CLASS/PACKAGE_BOTTOM" "[Shape] Package Geometry/Place_Bound_Bottom ((14988.03 -6580.0) (15031.65 -6538.0))" "[Shape] Package Geometry/Place_Bound_Bottom ((14915.59 -6647.0) (15087.61 -6505.24))" list(14988.030000 -6580.000000) nil)@@@list("liquid_ni" "2014/02/18 09:29:10" nil "s0dcoa16607a" "5s-impbw-cs.104")@@@list("jake_ma" "2014/02/18 09:48:50" nil "s0dcoa89107" "5s-impbw-cs.104") | list("[Package] BOTTOM" "Pkg to Pkg Spacing" "0 MIL [PACKAGE_HEIGHT_MIN]" "2 MIL" "-2.00 MIL" "DRC ERROR CLASS/PACKAGE_BOTTOM" "[Shape] Package Geometry/Place_Bound_Bottom ((14988.73 -6613.0) (15032.35 -6571.0))" "[Shape] Package Geometry/Place_Bound_Bottom ((14988.03 -6580.0) (15031.65 -6538.0))" list(14988.730000 -6571.000000) nil)@@@list("liquid_ni" "2014/02/18 09:29:16" nil "s0dcoa16607a" "5s-impbw-cs.104")@@@list("jake_ma" "2014/02/18 09:49:05" nil "s0dcoa89107" "5s-impbw-cs.104") | list("[Package] BOTTOM" "Pkg to Pkg Spacing" "0 MIL [PACKAGE_HEIGHT_MIN]" "39.37 MIL" "-39.37 MIL" "DRC ERROR CLASS/PACKAGE_BOTTOM" "[Shape] Package Geometry/Place_Bound_Bottom ((14988.73 -6613.0) (15032.35 -6571.0))" "[Shape] Package Geometry/Place_Bound_Bottom ((14915.59 -6647.0) (15087.61 -6505.24))" list(14988.730000 -6613.000000) nil)@@@list("liquid_ni" "2014/02/18 09:29:10" nil "s0dcoa16607a" "5s-impbw-cs.104")@@@list("jake_ma" "2014/02/18 09:48:49" nil "s0dcoa89107" "5s-impbw-cs.104") | list("[Package] BOTTOM" "Pkg to Pkg Spacing" "0 MIL [PACKAGE_HEIGHT_MIN]" "2 MIL" "-2.00 MIL" "DRC ERROR CLASS/PACKAGE_BOTTOM" "[Shape] Package Geometry/Place_Bound_Bottom ((14967.94 -7108.98) (15209.6 -6967.24))" "[Shape] Package Geometry/Place_Bound_Bottom ((15036.71 -7044.21) (15078.71 -7000.59))" list(15036.710000 -7044.210000) nil)@@@list("liquid_ni" "2014/02/18 09:29:16" nil "s0dcoa16607a" "5s-impbw-cs.104")@@@list("jake_ma" "2014/02/18 09:49:06" nil "s0dcoa89107" "5s-impbw-cs.104") | list("[Package] BOTTOM" "Pkg to Pkg Spacing" "0 MIL [PACKAGE_HEIGHT_MIN]" "2 MIL" "-2.00 MIL" "DRC ERROR CLASS/PACKAGE_BOTTOM" "[Shape] Package Geometry/Place_Bound_Bottom ((15037.09 -7078.02) (15079.09 -7034.4))" "[Shape] Package Geometry/Place_Bound_Bottom ((15036.71 -7044.21) (15078.71 -7000.59))" list(15037.090000 -7034.400000) nil)@@@list("liquid_ni" "2014/02/18 09:29:17" nil "s0dcoa16607a" "5s-impbw-cs.104")@@@list("jake_ma" "2014/02/18 09:49:08" nil "s0dcoa89107" "5s-impbw-cs.104") | list("[Package] BOTTOM" "Pkg to Pkg Spacing" "0 MIL [PACKAGE_HEIGHT_MIN]" "2 MIL" "-2.00 MIL" "DRC ERROR CLASS/PACKAGE_BOTTOM" "[Shape] Package Geometry/Place_Bound_Bottom ((14967.94 -7108.98) (15209.6 -6967.24))" "[Shape] Package Geometry/Place_Bound_Bottom ((15037.09 -7078.02) (15079.09 -7034.4))" list(15037.090000 -7078.020000) nil)@@@list("liquid_ni" "2014/02/18 09:29:17" nil "s0dcoa16607a" "5s-impbw-cs.104")@@@list("jake_ma" "2014/02/18 09:49:09" nil "s0dcoa89107" "5s-impbw-cs.104") | list("[Electrical] ALL" "Diffpair Max Uncoupled Length" "200 MIL [DIFFP_UNCOUPLED_LENGTH]" "318.35 MIL" "-118.35 MIL" "DRC ERROR CLASS/ALL" "[PinPair] <uTiL>cId3202<uTiL>.2:<uTiL>cId3248<uTiL>.AP8 ((15978.22 -5827.3) (11304.64 -6838.61))" "[PinPair] <uTiL>cId3202<uTiL>.3:<uTiL>cId3248<uTiL>.AR8 ((15978.22 -5858.79) (11330.24 -6838.61))" list(15978.220000 -5858.790000) nil)@@@list("liquid_ni" "2014/02/18 09:28:24" nil "s0dcoa16607a" "5s-impbw-cs.104")@@@list("jake_ma" "2014/02/18 09:45:53" nil "s0dcoa89107" "5s-impbw-cs.104") | list("[Package] BOTTOM" "Pkg to Place Keepin Spacing" "0 MIL [NONE]" "0 MIL" "0.00 MIL" "DRC ERROR CLASS/PACKAGE_BOTTOM" "[Shape] Package Keepin/All ((9791.94 -9293.68) (17182.26 -5761.63))" "[Shape] Package Geometry/Place_Bound_Bottom ((15843.14 -6197.45) (16022.72 -5709.11))" list(15987.270000 -5761.630000) nil)@@@list("liquid_ni" "2014/02/18 09:29:18" nil "s0dcoa16607a" "5s-impbw-cs.104")@@@list("jake_ma" "2014/02/18 09:52:54" nil "s0dcoa89107" "5s-impbw-cs.104") | list("[Package] BOTTOM" "Pkg to Pkg Spacing" "0 MIL [PACKAGE_HEIGHT_MIN]" "21.65 MIL" "-21.65 MIL" "DRC ERROR CLASS/PACKAGE_BOTTOM" "[Shape] Package Geometry/Place_Bound_Bottom ((16076.49 -6041.88) (16147.75 -5915.5))" "[Shape] Package Geometry/Place_Bound_Bottom ((16068.81 -6039.71) (16155.43 -5917.67))" list(16076.490000 -6039.710000) nil)@@@list("liquid_ni" "2014/02/18 09:29:12" nil "s0dcoa16607a" "5s-impbw-cs.104")@@@list("jake_ma" "2014/02/18 09:48:54" nil "s0dcoa89107" "5s-impbw-cs.104") | list("[Electrical] ALL" "Diffpair Max Uncoupled Length" "200 MIL [DIFFP_UNCOUPLED_LENGTH]" "204.06 MIL" "-4.06 MIL" "DRC ERROR CLASS/ALL" "[PinPair] <uTiL>cId3239<uTiL>.6:<uTiL>cId3248<uTiL>.B47 ((16175.79 -8284.85) (10580.16 -7786.44))" "[PinPair] <uTiL>cId3239<uTiL>.7:<uTiL>cId3248<uTiL>.A47 ((16160.04 -8284.85) (10554.56 -7786.44))" list(16160.040000 -8284.850000) nil)@@@list("liquid_ni" "2014/02/18 09:28:10" nil "s0dcoa16607a" "5s-impbw-cs.104")@@@list("jake_ma" "2014/02/18 09:45:24" nil "s0dcoa89107" "5s-impbw-cs.104") | list("[Electrical] ALL" "Diffpair Max Uncoupled Length" "200 MIL [DIFFP_UNCOUPLED_LENGTH]" "286.81 MIL" "-86.81 MIL" "DRC ERROR CLASS/ALL" "[PinPair] <uTiL>cId3248<uTiL>.A45:<uTiL>cId3239<uTiL>.60 ((10554.56 -7742.08) (16287.99 -8381.3))" "[PinPair] <uTiL>cId3248<uTiL>.B45:<uTiL>cId3239<uTiL>.61 ((10580.16 -7742.08) (16287.99 -8365.55))" list(16287.990000 -8365.550000) nil)@@@list("liquid_ni" "2014/02/18 09:28:16" nil "s0dcoa16607a" "5s-impbw-cs.104")@@@list("jake_ma" "2014/02/18 09:45:38" nil "s0dcoa89107" "5s-impbw-cs.104") | list("[Package] BOTTOM" "Pkg to Place Keepin Spacing" "0 MIL [NONE]" "0 MIL" "0.00 MIL" "DRC ERROR CLASS/PACKAGE_BOTTOM" "[Shape] Package Keepin/All ((9791.94 -9293.68) (17182.26 -5761.63))" "[Shape] Package Geometry/Place_Bound_Bottom ((15402.31 -9134.22) (16493.13 -8942.31))" list(16473.600000 -9134.220000) nil)@@@list("liquid_ni" "2014/02/18 09:29:20" nil "s0dcoa16607a" "5s-impbw-cs.104")@@@list("jake_ma" "2014/02/18 09:52:57" nil "s0dcoa89107" "5s-impbw-cs.104") | list("[Electrical] ALL" "Diffpair Max Uncoupled Length" "200 MIL [DIFFP_UNCOUPLED_LENGTH]" "297.92 MIL" "-97.92 MIL" "DRC ERROR CLASS/ALL" "[PinPair] <uTiL>cId3778<uTiL>.34:<uTiL>cId3248<uTiL>.C55 ((16563.0 -7366.1) (10605.76 -7983.88))" "[PinPair] <uTiL>cId3778<uTiL>.32:<uTiL>cId3248<uTiL>.C54 ((16563.0 -7385.79) (10618.56 -7961.7))" list(16563.000000 -7385.790000) nil)@@@list("liquid_ni" "2014/02/18 09:28:09" nil "s0dcoa16607a" "5s-impbw-cs.104")@@@list("jake_ma" "2014/02/18 09:45:23" nil "s0dcoa89107" "5s-impbw-cs.104") | list("[Electrical] ALL" "Diffpair Max Uncoupled Length" "200 MIL [DIFFP_UNCOUPLED_LENGTH]" "320.28 MIL" "-120.28 MIL" "DRC ERROR CLASS/ALL" "[PinPair] <uTiL>cId3778<uTiL>.26:<uTiL>cId3248<uTiL>.B58 ((16563.0 -7444.84) (10592.96 -8060.42))" "[PinPair] <uTiL>cId3778<uTiL>.28:<uTiL>cId3248<uTiL>.C58 ((16563.0 -7425.16) (10618.56 -8060.42))" list(16563.000000 -7425.160000) nil)@@@list("liquid_ni" "2014/02/18 09:28:05" nil "s0dcoa16607a" "5s-impbw-cs.104")@@@list("jake_ma" "2014/02/18 09:45:15" nil "s0dcoa89107" "5s-impbw-cs.104") | list("[Package] BOTTOM" "Pkg to Pkg Spacing" "0 MIL [PACKAGE_HEIGHT_MIN]" "120 MIL" "-120.00 MIL" "DRC ERROR CLASS/PACKAGE_BOTTOM" "[Shape] Package Geometry/Place_Bound_Bottom ((16539.92 -6035.67) (17205.92 -5767.29))" "[Shape] Package Geometry/Place_Bound_Bottom ((16852.93 -6307.5) (17247.26 -6031.28))" list(16852.930000 -6035.670000) nil)@@@list("liquid_ni" "2014/02/18 09:29:09" nil "s0dcoa16607a" "5s-impbw-cs.104")@@@list("jake_ma" "2014/02/18 09:48:41" nil "s0dcoa89107" "5s-impbw-cs.104") | list("[Electrical] ALL" "Diffpair Max Uncoupled Length" "200 MIL [DIFFP_UNCOUPLED_LENGTH]" "264.36 MIL" "-64.36 MIL" "DRC ERROR CLASS/ALL" "[PinPair] <uTiL>cId3778<uTiL>.27:<uTiL>cId3248<uTiL>.A55 ((16861.23 -7435.0) (10554.56 -7983.88))" "[PinPair] <uTiL>cId3778<uTiL>.25:<uTiL>cId3248<uTiL>.B55 ((16861.23 -7454.68) (10580.16 -7983.88))" list(16861.230000 -7454.680000) nil)@@@list("liquid_ni" "2014/02/18 09:28:08" nil "s0dcoa16607a" "5s-impbw-cs.104")@@@list("jake_ma" "2014/02/18 09:45:20" nil "s0dcoa89107" "5s-impbw-cs.104") | list("[Electrical] ALL" "Diffpair Max Uncoupled Length" "200 MIL [DIFFP_UNCOUPLED_LENGTH]" "216.2 MIL" "-16.20 MIL" "DRC ERROR CLASS/ALL" "[PinPair] <uTiL>cId3778<uTiL>.21:<uTiL>cId3248<uTiL>.B57 ((16861.23 -7494.05) (10580.16 -8038.24))" "[PinPair] <uTiL>cId3778<uTiL>.19:<uTiL>cId3248<uTiL>.A57 ((16861.23 -7513.74) (10554.56 -8038.24))" list(16861.230000 -7513.740000) nil)@@@list("liquid_ni" "2014/02/18 09:28:07" nil "s0dcoa16607a" "5s-impbw-cs.104")@@@list("jake_ma" "2014/02/18 09:45:17" nil "s0dcoa89107" "5s-impbw-cs.104") | list("[Electrical] ALL" "Diffpair Max Uncoupled Length" "200 MIL [DIFFP_UNCOUPLED_LENGTH]" "404.24 MIL" "-204.24 MIL" "DRC ERROR CLASS/ALL" "[PinPair] <uTiL>cId3248<uTiL>.AN11:<uTiL>cId3778<uTiL>.3 ((11279.04 -6914.14) (16861.23 -7671.22))" "[PinPair] <uTiL>cId3248<uTiL>.AP11:<uTiL>cId3778<uTiL>.5 ((11304.64 -6914.14) (16861.23 -7651.53))" list(16861.230000 -7651.530000) nil)@@@list("liquid_ni" "2014/02/18 09:28:43" nil "s0dcoa16607a" "5s-impbw-cs.104")@@@list("jake_ma" "2014/02/18 09:46:56" nil "s0dcoa89107" "5s-impbw-cs.104") | list("[Package] TOP" "Pkg to Place Keepout Spacing" "0 MIL [PACKAGE_HEIGHT_MIN]" "120 MIL" "-120.00 MIL" "DRC ERROR CLASS/PACKAGE_TOP" "[Shape] Package Keepout/Top ((16990.59 -7288.27) (17272.59 -6257.16))" "[Shape] Package Geometry/Place_Bound_Top ((16852.93 -6307.5) (17247.26 -6031.28))" list(17012.640000 -6307.500000) nil)@@@list("liquid_ni" "2014/02/18 09:28:55" nil "s0dcoa16607a" "5s-impbw-cs.104")@@@list("jake_ma" "2014/02/18 09:47:31" nil "s0dcoa89107" "5s-impbw-cs.104") | list("[Package] BOTTOM" "Pkg to Place Keepin Spacing" "0 MIL [NONE]" "0 MIL" "0.00 MIL" "DRC ERROR CLASS/PACKAGE_BOTTOM" "[Shape] Package Keepin/All ((9791.94 -9293.68) (17182.26 -5761.63))" "[Shape] Package Geometry/Place_Bound_Bottom ((16813.55 -9201.2) (17129.15 -8806.86))" list(17088.570000 -8806.860000) nil)@@@list("liquid_ni" "2014/02/18 09:29:06" nil "s0dcoa16607a" "5s-impbw-cs.104")@@@list("jake_ma" "2014/02/18 09:52:47" nil "s0dcoa89107" "5s-impbw-cs.104") | list("[Package] TOP" "Pkg to Place Keepin Spacing" "0 MIL [NONE]" "0 MIL" "0.00 MIL" "DRC ERROR CLASS/PACKAGE_TOP" "[Shape] Package Keepin/All ((9791.94 -9293.68) (17182.26 -5761.63))" "[Shape] Package Geometry/Place_Bound_Top ((16813.55 -9201.2) (17129.15 -8806.86))" list(17088.570000 -8806.860000) nil)@@@list("liquid_ni" "2014/02/18 09:28:53" nil "s0dcoa16607a" "5s-impbw-cs.104")@@@list("jake_ma" "2014/02/18 09:51:37" nil "s0dcoa89107" "5s-impbw-cs.104") | list("[Package] BOTTOM" "4.Pkg to Place Keepin Spacing" "0 MIL [NONE]" "2571.97 MIL" "-2571.97 MIL" "DRC ERROR CLASS/PACKAGE_BOTTOM" "[Shape] Package Keepin/All ((9791.94 -9293.68) (17182.26 -5761.63))" "[Shape] Package Geometry/Place_Bound_Bottom ((17548.15 -3215.82) (17648.11 -3115.85))" list(17182.260000 -5761.630000) nil)@@@list("alina_kuo" "2014/03/04 17:57:42" nil "ALINA_KUO-PC1" "5s-impbw-cs-corse.a00")@@@list("johnson_wang" "2014/03/10 10:27:13" nil "johnson_wang-pc" "5s-impbw-cs.a00") | list("[Package] BOTTOM" "Pkg to Place Keepin Spacing" "0 MIL [NONE]" "2670.99 MIL" "-2670.99 MIL" "DRC ERROR CLASS/PACKAGE_BOTTOM" "[Shape] Package Keepin/All ((9791.94 -9293.68) (17182.26 -5761.63))" "[Shape] Package Geometry/Place_Bound_Bottom ((17548.15 -3115.82) (17648.11 -3015.85))" list(17182.260000 -5761.630000) nil)@@@list("liquid_ni" "2014/02/18 09:29:22" nil "s0dcoa16607a" "5s-impbw-cs.104")@@@list("jake_ma" "2014/02/18 09:53:04" nil "s0dcoa89107" "5s-impbw-cs.104") | list("[Package] TOP" "2.Pkg to Place Keepin Spacing" "0 MIL [NONE]" "2770.08 MIL" "-2770.08 MIL" "DRC ERROR CLASS/PACKAGE_TOP" "[Shape] Package Keepin/All ((9791.94 -9293.68) (17182.26 -5761.63))" "[Shape] Package Geometry/Place_Bound_Top ((17548.15 -3015.82) (17648.11 -2915.85))" list(17182.260000 -5761.630000) nil)@@@list("alina_kuo" "2014/03/04 17:57:35" nil "ALINA_KUO-PC1" "5s-impbw-cs-corse.a00")@@@list("johnson_wang" "2014/03/10 10:27:10" nil "johnson_wang-pc" "5s-impbw-cs.a00") | list("[Package] TOP" "Pkg to Place Keepin Spacing" "0 MIL [NONE]" "2869.24 MIL" "-2869.24 MIL" "DRC ERROR CLASS/PACKAGE_TOP" "[Shape] Package Keepin/All ((9791.94 -9293.68) (17182.26 -5761.63))" "[Shape] Package Geometry/Place_Bound_Top ((17548.15 -2915.82) (17648.11 -2815.85))" list(17182.260000 -5761.630000) nil)@@@list("liquid_ni" "2014/02/18 09:29:02" nil "s0dcoa16607a" "5s-impbw-cs.104")@@@list("jake_ma" "2014/02/18 09:52:39" nil "s0dcoa89107" "5s-impbw-cs.104") | list("[Package] TOP" "Pkg to Place Keepin Spacing" "0 MIL [NONE]" "3465.68 MIL" "-3465.68 MIL" "DRC ERROR CLASS/PACKAGE_TOP" "[Shape] Package Keepin/All ((9791.94 -9293.68) (17182.26 -5761.63))" "[Shape] Package Geometry/Place_Bound_Top ((17503.13 -2310.84) (17693.13 -2120.84))" list(17182.260000 -5761.630000) nil)@@@list("liquid_ni" "2014/02/18 09:29:00" nil "s0dcoa16607a" "5s-impbw-cs.104")@@@list("jake_ma" "2014/02/18 09:52:32" nil "s0dcoa89107" "5s-impbw-cs.104") | list("[Package] BOTTOM" "Pkg to Place Keepin Spacing" "0 MIL [NONE]" "0 MIL" "0.00 MIL" "DRC ERROR CLASS/PACKAGE_BOTTOM" "[Shape] Package Keepin/All ((9791.94 -9293.68) (17182.26 -5761.63))" "[Shape] Package Geometry/Place_Bound_Bottom ((16539.92 -6035.67) (17205.92 -5767.29))" list(17182.260000 -5921.690000) nil)@@@list("liquid_ni" "2014/02/18 09:29:19" nil "s0dcoa16607a" "5s-impbw-cs.104")@@@list("jake_ma" "2014/02/18 09:52:55" nil "s0dcoa89107" "5s-impbw-cs.104") | list("[Package] BOTTOM" "Pkg to Place Keepin Spacing" "0 MIL [NONE]" "0 MIL" "0.00 MIL" "DRC ERROR CLASS/PACKAGE_BOTTOM" "[Shape] Package Keepin/All ((9791.94 -9293.68) (17182.26 -5761.63))" "[Shape] Package Geometry/Place_Bound_Bottom ((17007.77 -7921.14) (17529.82 -6305.4))" list(17182.260000 -6305.400000) nil)@@@list("liquid_ni" "2014/02/18 09:29:19" nil "s0dcoa16607a" "5s-impbw-cs.104")@@@list("jake_ma" "2014/02/18 09:52:56" nil "s0dcoa89107" "5s-impbw-cs.104") | list("[Package] BOTTOM" "Pkg to Place Keepin Spacing" "0 MIL [NONE]" "0 MIL" "0.00 MIL" "DRC ERROR CLASS/PACKAGE_BOTTOM" "[Shape] Package Keepin/All ((9791.94 -9293.68) (17182.26 -5761.63))" "[Shape] Package Geometry/Place_Bound_Bottom ((16852.93 -6307.5) (17247.26 -6031.28))" list(17182.260000 -6307.500000) nil)@@@list("liquid_ni" "2014/02/18 09:29:09" nil "s0dcoa16607a" "5s-impbw-cs.104")@@@list("jake_ma" "2014/02/18 09:52:53" nil "s0dcoa89107" "5s-impbw-cs.104") | list("[Package] TOP" "Pkg to Place Keepin Spacing" "0 MIL [NONE]" "0 MIL" "0.00 MIL" "DRC ERROR CLASS/PACKAGE_TOP" "[Shape] Package Keepin/All ((9791.94 -9293.68) (17182.26 -5761.63))" "[Shape] Package Geometry/Place_Bound_Top ((16852.93 -6307.5) (17247.26 -6031.28))" list(17182.260000 -6307.500000) nil)@@@list("liquid_ni" "2014/02/18 09:28:55" nil "s0dcoa16607a" "5s-impbw-cs.104")@@@list("jake_ma" "2014/02/18 09:51:47" nil "s0dcoa89107" "5s-impbw-cs.104") | list("[Package] BOTTOM" "3.Pkg to Place Keepin Spacing" "0 MIL [NONE]" "365.89 MIL" "-365.89 MIL" "DRC ERROR CLASS/PACKAGE_BOTTOM" "[Shape] Package Keepin/All ((9791.94 -9293.68) (17182.26 -5761.63))" "[Shape] Package Geometry/Place_Bound_Bottom ((17548.15 -8238.67) (17648.11 -8138.7))" list(17182.260000 -8188.680000) nil)@@@list("alina_kuo" "2014/03/04 17:57:40" nil "ALINA_KUO-PC1" "5s-impbw-cs-corse.a00")@@@list("johnson_wang" "2014/03/10 10:27:11" nil "johnson_wang-pc" "5s-impbw-cs.a00") | list("[Package] BOTTOM" "Pkg to Place Keepin Spacing" "0 MIL [NONE]" "365.89 MIL" "-365.89 MIL" "DRC ERROR CLASS/PACKAGE_BOTTOM" "[Shape] Package Keepin/All ((9791.94 -9293.68) (17182.26 -5761.63))" "[Shape] Package Geometry/Place_Bound_Bottom ((17548.15 -8338.67) (17648.11 -8238.7))" list(17182.260000 -8288.680000) nil)@@@list("liquid_ni" "2014/02/18 09:29:21" nil "s0dcoa16607a" "5s-impbw-cs.104")@@@list("jake_ma" "2014/02/18 09:52:59" nil "s0dcoa89107" "5s-impbw-cs.104") | list("[Package] TOP" "1.Pkg to Place Keepin Spacing" "0 MIL [NONE]" "365.89 MIL" "-365.89 MIL" "DRC ERROR CLASS/PACKAGE_TOP" "[Shape] Package Keepin/All ((9791.94 -9293.68) (17182.26 -5761.63))" "[Shape] Package Geometry/Place_Bound_Top ((17548.15 -8438.67) (17648.11 -8338.7))" list(17182.260000 -8388.680000) nil)@@@list("alina_kuo" "2014/03/04 17:57:30" nil "ALINA_KUO-PC1" "5s-impbw-cs-corse.a00")@@@list("johnson_wang" "2014/03/10 10:27:09" nil "johnson_wang-pc" "5s-impbw-cs.a00") | list("[Package] TOP" "Pkg to Place Keepin Spacing" "0 MIL [NONE]" "365.89 MIL" "-365.89 MIL" "DRC ERROR CLASS/PACKAGE_TOP" "[Shape] Package Keepin/All ((9791.94 -9293.68) (17182.26 -5761.63))" "[Shape] Package Geometry/Place_Bound_Top ((17548.15 -8538.67) (17648.11 -8438.7))" list(17182.260000 -8488.680000) nil)@@@list("liquid_ni" "2014/02/18 09:29:00" nil "s0dcoa16607a" "5s-impbw-cs.104")@@@list("jake_ma" "2014/02/18 09:52:36" nil "s0dcoa89107" "5s-impbw-cs.104") | list("[Package] BOTTOM" "Pkg to Place Keepin Spacing" "0 MIL [NONE]" "0 MIL" "0.00 MIL" "DRC ERROR CLASS/PACKAGE_BOTTOM" "[Shape] Package Keepin/All ((9791.94 -9293.68) (17182.26 -5761.63))" "[Shape] Package Geometry/Place_Bound_Bottom ((16940.18 -8707.01) (17208.04 -8553.22))" list(17182.260000 -8574.690000) nil)@@@list("liquid_ni" "2014/02/18 09:29:04" nil "s0dcoa16607a" "5s-impbw-cs.104")@@@list("jake_ma" "2014/02/18 09:52:43" nil "s0dcoa89107" "5s-impbw-cs.104") | list("[Package] TOP" "Pkg to Place Keepin Spacing" "0 MIL [NONE]" "414.13 MIL" "-414.13 MIL" "DRC ERROR CLASS/PACKAGE_TOP" "[Shape] Package Keepin/All ((9791.94 -9293.68) (17182.26 -5761.63))" "[Shape] Package Geometry/Place_Bound_Top ((17503.13 -9233.68) (17693.13 -9043.68))" list(17182.260000 -8781.860000) nil)@@@list("liquid_ni" "2014/02/18 09:28:59" nil "s0dcoa16607a" "5s-impbw-cs.104")@@@list("jake_ma" "2014/02/18 09:52:09" nil "s0dcoa89107" "5s-impbw-cs.104") | list("[Package] BOTTOM" "Pkg to Pkg Spacing" "0 MIL [PACKAGE_HEIGHT_MIN]" "120 MIL" "-120.00 MIL" "DRC ERROR CLASS/PACKAGE_BOTTOM" "[Shape] Package Geometry/Place_Bound_Bottom ((17007.77 -7921.14) (17529.82 -6305.4))" "[Shape] Package Geometry/Place_Bound_Bottom ((16852.93 -6307.5) (17247.26 -6031.28))" list(17247.260000 -6305.400000) nil)@@@list("liquid_ni" "2014/02/18 09:29:09" nil "s0dcoa16607a" "5s-impbw-cs.104")@@@list("jake_ma" "2014/02/18 09:48:39" nil "s0dcoa89107" "5s-impbw-cs.104")
